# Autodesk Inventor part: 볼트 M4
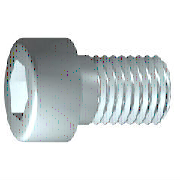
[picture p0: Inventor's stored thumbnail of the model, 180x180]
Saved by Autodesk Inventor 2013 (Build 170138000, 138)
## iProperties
IsCustomPart: 1
Created: 2012-02
Part Number: 볼트 M4
Material: 강철, 연강
Description: 6각머리 태핑 나사
Document SubType Name: Modeling
Standard: KS B 1003
Designer: mduedu
Standards Organization: KS
Language: ko-KR
Size Designation: M 4 x 10
Categories: <MemberInstance><Categories><Category DisplayName="조임쇠" InternalName="e4da775c-781d-43d5-af7c-5136215cf5a6" Mnemonic="FSTN"><Category DisplayName="볼트" InternalN
Density: 7.86 g/cm^3
Mass: 2.0371 g
Surface Area: 3.0572 cm^2
Volume: 0.259174 cm^3
Author: mduedu
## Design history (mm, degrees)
sketch "스케치1"
  geometry: L1 (-1, 0)-(10, 0); L2 (10, 0)-(10, 2); L3 (10, 2)-(1.75, 2); L4 (1.75, 2)-(1.32, 2); L5 (1.32, 2)-(0, 2); L6 (0, 2)-(0, 3.5); L7 (0, 3.5)-(-4, 3.5); L8 (-4, 3.5)-(-4, 1.732); L9 (-4, 1.732)-(-2, 1.732); L10 (-2, 1.732)-(-1, 0); L11 (-6.8, 0)-(12.8, 0) reference; L12 (0, -0.7)-(0, 4.2) reference; L13 (1.75, 2)-(0, 2)
  constraints: 22 end point, 6 parallel, 2 collinear, 2 perpendicular, 1 horizontal, 1 point on line
  dimensions: "d1" = 8.25 distance from line of L3.end L2 (= GEL); "d2" = 0.42952 distance of L4.end L3.end (computed from GAL); "d3" = 4 distance between parallel lines of L8 L6 (= KOH); "d4" = 2 distance of L8.end L9.end (= INTI); "d5" = 60 deg angle of L10 L1; "d6" = 4 diameter of L3 L1 (= GD); "d7" = 4 diameter of L5 L1 (= BDM); "d8" = 3.4641 diameter of L9 L1 (= 1.1547 x SW); "d9" = 7 diameter of L7 L1 (= KOD); "d26" = 10 distance between parallel lines of L12 L2 (= NLG)
revolve "본체" sketch "스케치1" stored, may be unused: angle "d10" = 90 deg
sketch "스케치2"
  geometry: L1 (0, -4.9)-(0, 4.9) reference; L2 (-4.9, 0)-(4.9, 0) reference; L3 (1.732, 0)-(0.866, -1.5); L4 (0.866, -1.5)-(-0.866, -1.5); L5 (-0.866, -1.5)-(-1.732, 0); L6 (-1.732, 0)-(-0.866, 1.5); L7 (-0.866, 1.5)-(0.866, 1.5); L8 (0.866, 1.5)-(1.732, 0); 2 further points
  constraints: 12 end point, 1 coincident, 1 horizontal alignment, 1 point on line, 12 other
extrude "슬롯" join sketch "스케치2" stored distance "d11" = 10; taper "d12" = 0 deg
workplane "Work Plane1"
fillet "Fillet2" dims "d30" = 0.1 (= R)
body "Solid1"
fillet "모깎기1" dims "d17" = 0.4 (= RR)
feature "스레드" dims "d13" = 8.25 (= GEL), "d14" = 0
chamfer "모따기1" distance "d15" = 0.42941 (= -0.5 x SPD + 0.5 x GD); stored, may be unused: second distance "d16" = 0.42941 (= GUL), angle "d27" = 45 deg
other parameters: "GD" = 4 (= NND) [user parameter; used in 2 equation terms], "NLG" = 10 [user parameter; used in 1 equation term], "GEL" = 8.25 [user parameter; used in 2 equation terms], "KOD" = 7 [user parameter; used in 1 equation term], "KOH" = 4 [user parameter; used in 1 equation term], "INTI" = 2 [user parameter; used in 1 equation term], "GAL" = 0.42941 (= 0.61345 x PTC) [user parameter; used in 1 equation term], "GUL" = 0.42941 (= 0.61345 x PTC) [user parameter; used in 1 equation term], "BDM" = 4 (= NND) [user parameter; used in 1 equation term], "SW" = 3 [user parameter; used in 2 equation terms], "RR" = 0.4 [user parameter; used in 1 equation term], "SPD" = 3.14117 (= NND - 1.2269 x PTC) [user parameter; used in 1 equation term], "d19" = 0, "d28" = 0, "d29" = 0, "R" = 0.1 [user parameter; used in 1 equation term], "PHH" = 0.2 [user parameter], "GD1" = 3.14117 (= THREADDIA - 1.2269 x PTC) [user parameter], "THREADDIA" = 4 [user parameter; used in 1 equation term], "FAWI" = 45 deg [user parameter], "TPU" = 14.28571 (computed from PTC) [user parameter], "PTC" = 0.7 [user parameter; used in 5 equation terms], "NND" = 4 [user parameter; used in 3 equation terms], "TOA" = 30 deg [user parameter], "E0" = 3.465 (= 1.155 x SW) [user parameter]
